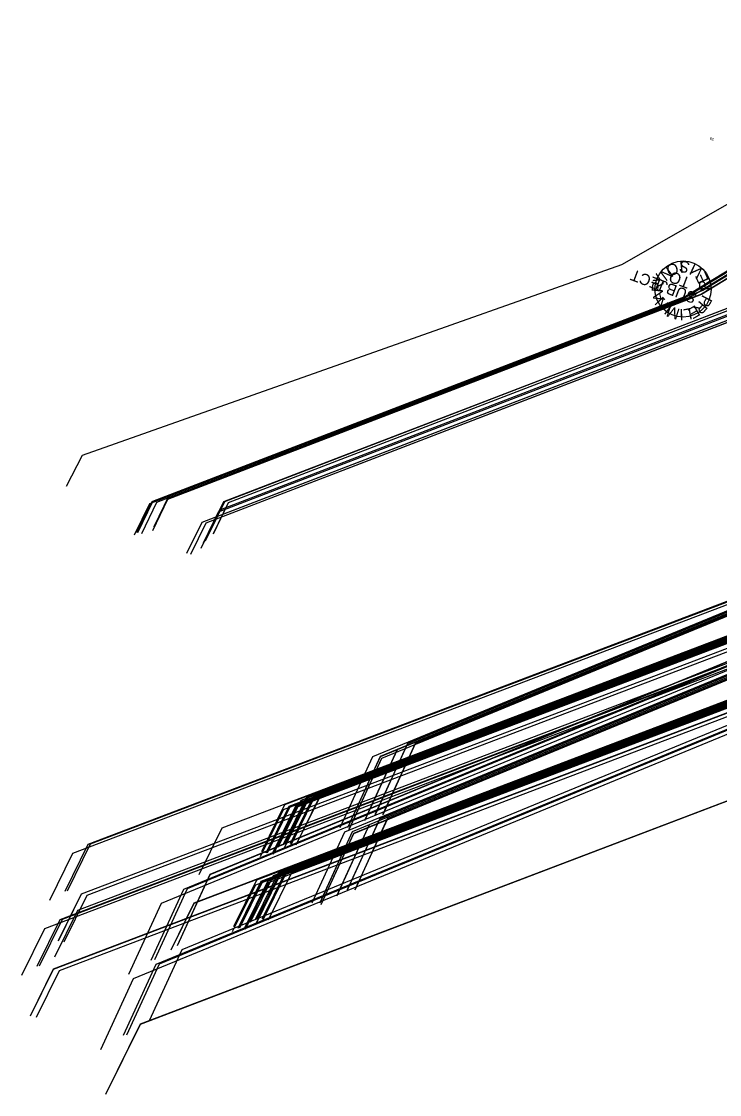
# Model space of a CAD drawing. Extents: x 1383350 to 1389654, y 1969292 to 1976308.
# Drawn here: x 1383350 to 1384913, y 1972123 to 1974524 of the extents above; entities that cross this region are included whole.
import ezdxf

# ---------------------------------------------------------------- set-up
doc = ezdxf.new("R2010")
doc.units = 0
for name, color, linetype in [('1', 7, 'Continuous'), ('R_Draft', 7, 'Continuous'), ('STAMP', 7, 'Continuous')]:
    doc.layers.add(name, color=color, linetype=linetype)

msp = doc.modelspace()

# ---------------------------------------------------------------- linework, layer by layer
at = {"layer": 'R_Draft'}
for p, q in [((1383486.4, 1973552.5), (1383450.4, 1973483.5)), ((1383486.3, 1973552.3), (1383450.4, 1973483.3)), ((1383486.3, 1973552.3), (1383450.4, 1973483.3)), ((1383680.3, 1973462.5), (1383646.2, 1973392.6)), ((1383680.2, 1973462.3), (1383646.2, 1973392.4)), ((1383680.2, 1973462.3), (1383646.2, 1973392.4)), ((1383637, 1973444.2), (1383602.9, 1973374.3)), ((1383637, 1973444.2), (1383602.9, 1973374.3)), ((1383637, 1973444.1), (1383602.9, 1973374.1)), ((1383641.8, 1973449.2), (1383607.7, 1973379.3)), ((1383643.9, 1973449.4), (1383609.8, 1973379.5)), ((1383643.9, 1973449.4), (1383609.8, 1973379.5)), ((1383643.9, 1973449.2), (1383609.8, 1973379.3)), ((1383652.7, 1973447.5), (1383618.6, 1973377.6)), ((1383652.7, 1973447.4), (1383618.6, 1973377.4)), ((1383652.7, 1973447.3), (1383618.6, 1973377.4)), ((1383677.4, 1973453.8), (1383643.3, 1973383.8)), ((1383677.4, 1973453.7), (1383643.3, 1973383.8)), ((1383677.4, 1973453.9), (1383643.4, 1973384)), ((1383802.3, 1973448.6), (1383768.3, 1973378.7)), ((1383804.4, 1973448.8), (1383770.3, 1973378.9)), ((1383804.4, 1973448.7), (1383770.3, 1973378.8)), ((1383804.4, 1973448.9), (1383770.4, 1973378.9)), ((1383813.2, 1973446.9), (1383779.1, 1973377)), ((1383813.2, 1973446.8), (1383779.1, 1973376.8)), ((1383813.2, 1973446.8), (1383779.1, 1973376.9)), ((1383785.5, 1973414.3), (1383751.4, 1973344.4)), ((1383785.5, 1973414.5), (1383751.5, 1973344.6)), ((1383785.6, 1973414.5), (1383751.5, 1973344.6)), ((1383790.7, 1973425.8), (1383756.6, 1973355.9)), ((1383790.8, 1973426), (1383756.7, 1973356)), ((1383790.8, 1973426), (1383756.7, 1973356.1)), ((1383795.6, 1973430.9), (1383761.5, 1973361)), ((1383753.9, 1973402.9), (1383719.8, 1973333)), ((1383753.9, 1973402.9), (1383719.8, 1973333)), ((1383753.9, 1973402.8), (1383719.8, 1973332.9)), ((1383762.7, 1973401), (1383728.6, 1973331.1)), ((1383762.7, 1973400.9), (1383728.6, 1973331)), ((1383762.7, 1973400.8), (1383728.6, 1973330.9)), ((1384214.4, 1972907.3), (1384141.4, 1972748.3)), ((1384214.4, 1972907.2), (1384141.4, 1972748.2)), ((1384214.5, 1972907.7), (1384141.5, 1972748.6)), ((1384231.6, 1972907.5), (1384158.6, 1972748.4)), ((1384231.7, 1972907.9), (1384158.7, 1972748.8)), ((1384231.6, 1972907.5), (1384158.7, 1972748.5)), ((1384191.2, 1972894), (1384118.2, 1972735)), ((1384191.3, 1972894.4), (1384118.3, 1972735.3)), ((1384191.3, 1972894.4), (1384118.3, 1972735.4)), ((1384136, 1972878.1), (1384063, 1972719.1)), ((1384153.2, 1972878.3), (1384080.2, 1972719.3)), ((1384153.3, 1972878.8), (1384080.3, 1972719.7)), ((1384153.3, 1972878.7), (1384080.3, 1972719.7)), ((1384155.9, 1972874.7), (1384082.9, 1972715.6)), ((1384155.8, 1972874.3), (1384082.9, 1972715.2)), ((1384155.9, 1972874.3), (1384082.9, 1972715.3)), ((1383988.4, 1972788.2), (1383936.9, 1972683.5)), ((1383991.5, 1972788.7), (1383940, 1972684)), ((1383991.5, 1972788.6), (1383940, 1972684)), ((1383991.5, 1972788.4), (1383940, 1972683.7)), ((1384003, 1972788.5), (1383951.5, 1972683.8)), ((1384003, 1972788.5), (1383951.5, 1972683.8)), ((1384002.9, 1972788.2), (1383951.5, 1972683.6)), ((1383938.7, 1972770.6), (1383887.2, 1972666)), ((1383948.7, 1972767.3), (1383897.3, 1972662.6)), ((1383951.9, 1972767.8), (1383900.4, 1972663.1)), ((1383951.9, 1972767.7), (1383900.4, 1972663)), ((1383951.8, 1972767.5), (1383900.4, 1972662.8)), ((1383963.3, 1972767.3), (1383911.8, 1972662.6)), ((1383963.4, 1972767.6), (1383911.9, 1972662.9)), ((1383963.4, 1972767.6), (1383911.9, 1972662.9)), ((1383965, 1972764.6), (1383913.5, 1972659.9)), ((1383965, 1972764.6), (1383913.5, 1972659.9)), ((1383965.1, 1972764.8), (1383913.6, 1972660.2)), ((1383975.8, 1972780.2), (1383924.3, 1972675.6)), ((1383989, 1972777.4), (1383937.5, 1972672.7)), ((1383989, 1972777.3), (1383937.5, 1972672.6)), ((1383989, 1972777.1), (1383937.5, 1972672.4)), ((1384004.7, 1972785.8), (1383953.2, 1972681.1)), ((1384004.6, 1972785.5), (1383953.2, 1972680.8)), ((1384004.7, 1972785.5), (1383953.2, 1972680.8)), ((1384016.1, 1972785.4), (1383964.6, 1972680.7)), ((1384016.1, 1972785.3), (1383964.6, 1972680.6)), ((1384016.2, 1972785.6), (1383964.7, 1972680.9)), ((1383936.2, 1972759.3), (1383884.7, 1972654.6)), ((1384151.9, 1972739), (1384078.9, 1972579.9)), ((1384151.9, 1972739), (1384078.9, 1972580)), ((1384152, 1972739.4), (1384079, 1972580.3)), ((1384169.1, 1972739.2), (1384096.1, 1972580.2)), ((1384169.1, 1972739.2), (1384096.1, 1972580.2)), ((1384169.2, 1972739.6), (1384096.2, 1972580.6)), ((1383798.9, 1972718.8), (1383747.4, 1972614.2)), ((1383798.9, 1972718.6), (1383747.4, 1972613.9)), ((1383798.9, 1972718.6), (1383747.4, 1972613.9)), ((1384128.7, 1972725.7), (1384055.7, 1972566.7)), ((1384128.8, 1972726.2), (1384055.8, 1972567.1)), ((1384128.8, 1972726.1), (1384055.8, 1972567.1)), ((1384073.4, 1972709.9), (1384000.5, 1972550.8)), ((1384090.7, 1972710.1), (1384017.7, 1972551)), ((1384090.7, 1972710.5), (1384017.8, 1972551.4)), ((1384090.7, 1972710.4), (1384017.8, 1972551.4)), ((1384093.3, 1972706), (1384020.3, 1972547)), ((1384093.4, 1972706.4), (1384020.4, 1972547.4)), ((1384093.3, 1972706.1), (1384020.4, 1972547)), ((1383498.6, 1972681.9), (1383447.1, 1972577.2)), ((1383498.6, 1972681.8), (1383447.1, 1972577.2)), ((1383503.9, 1972682.5), (1383452.4, 1972577.8)), ((1383464.3, 1972661.6), (1383412.8, 1972556.9)), ((1383925.8, 1972619.9), (1383874.4, 1972515.3)), ((1383929, 1972620.4), (1383877.5, 1972515.7)), ((1383929, 1972620.4), (1383877.5, 1972515.7)), ((1383928.9, 1972620.1), (1383877.5, 1972515.4)), ((1383940.4, 1972620), (1383888.9, 1972515.3)), ((1383940.5, 1972620.2), (1383889, 1972515.5)), ((1383940.5, 1972620.2), (1383889, 1972515.6)), ((1383771.8, 1972614.6), (1383698.8, 1972455.6)), ((1383771.8, 1972614.5), (1383698.8, 1972455.5)), ((1383876.2, 1972602.4), (1383824.7, 1972497.7)), ((1383886.2, 1972599), (1383834.7, 1972494.3)), ((1383889.3, 1972599.2), (1383837.8, 1972494.5)), ((1383889.4, 1972599.5), (1383837.9, 1972494.8)), ((1383889.4, 1972599.4), (1383837.9, 1972494.8)), ((1383900.8, 1972599), (1383849.3, 1972494.4)), ((1383900.9, 1972599.3), (1383849.4, 1972494.6)), ((1383900.9, 1972599.3), (1383849.4, 1972494.6)), ((1383902.5, 1972596.3), (1383851, 1972491.6)), ((1383902.5, 1972596.3), (1383851, 1972491.6)), ((1383902.6, 1972596.6), (1383851.1, 1972491.9)), ((1383913.3, 1972612), (1383861.8, 1972507.3)), ((1383926.5, 1972609.1), (1383875, 1972504.4)), ((1383926.5, 1972609), (1383875, 1972504.4)), ((1383926.4, 1972608.8), (1383875, 1972504.1)), ((1383942.1, 1972617.2), (1383890.6, 1972512.5)), ((1383942.1, 1972617.2), (1383890.6, 1972512.6)), ((1383942.2, 1972617.5), (1383890.7, 1972512.8)), ((1383953.6, 1972617.1), (1383902.1, 1972512.4)), ((1383953.6, 1972617), (1383902.1, 1972512.4)), ((1383953.7, 1972617.3), (1383902.2, 1972512.6)), ((1383483.7, 1972570.8), (1383432.2, 1972466.1)), ((1383483.7, 1972570.8), (1383432.2, 1972466.2)), ((1383483.8, 1972571.1), (1383432.3, 1972466.4)), ((1383713.2, 1972581.6), (1383640.2, 1972422.5)), ((1383713.2, 1972581.6), (1383640.2, 1972422.6)), ((1383721.2, 1972582.8), (1383648.2, 1972423.7)), ((1383873.7, 1972591.1), (1383822.2, 1972486.4)), ((1383496.9, 1972567.9), (1383445.4, 1972463.2)), ((1383662.6, 1972549.8), (1383589.7, 1972390.8)), ((1383736.4, 1972550.6), (1383684.9, 1972445.9)), ((1383736.4, 1972550.3), (1383684.9, 1972445.6)), ((1383736.4, 1972550.3), (1383684.9, 1972445.6)), ((1383475.7, 1972534.5), (1383424.2, 1972429.8)), ((1383475.7, 1972534.5), (1383424.2, 1972429.8)), ((1383436.1, 1972513.6), (1383384.6, 1972408.9)), ((1383436.1, 1972513.6), (1383384.6, 1972408.9)), ((1383441.4, 1972514.2), (1383389.9, 1972409.5)), ((1383401.8, 1972493.3), (1383350.3, 1972388.6)), ((1383709.3, 1972446.3), (1383636.3, 1972287.2)), ((1383709.3, 1972446.3), (1383636.3, 1972287.3)), ((1383421.2, 1972402.8), (1383369.7, 1972298.1)), ((1383421.2, 1972402.6), (1383369.7, 1972297.9)), ((1383421.2, 1972402.5), (1383369.7, 1972297.9)), ((1383650.7, 1972413.4), (1383577.7, 1972254.3)), ((1383650.7, 1972413.3), (1383577.7, 1972254.3)), ((1383658.7, 1972414.5), (1383585.7, 1972255.4)), ((1383434.4, 1972399.6), (1383382.9, 1972295)), ((1383600.1, 1972381.5), (1383527.1, 1972222.5)), ((1383615.9, 1972279.6), (1383538.6, 1972122.5)), ((1383615.9, 1972279.6), (1383538.6, 1972122.6)), ((1383616, 1972280), (1383538.7, 1972123))]:
    msp.add_line(p, q, dxfattribs=at)
for points in [[(1387690, 1974523.2), (1386878, 1974003.2), (1384214.4, 1972907.3)], [(1387690, 1974523.1), (1386878, 1974003.2), (1384214.4, 1972907.2)], [(1387690.1, 1974523.5), (1386878.1, 1974003.6), (1384214.5, 1972907.7)], [(1387707.2, 1974523.4), (1386895.2, 1974003.4), (1384231.6, 1972907.5)], [(1387707.2, 1974523.3), (1386895.2, 1974003.4), (1384231.6, 1972907.5)], [(1387707.3, 1974523.8), (1386895.3, 1974003.8), (1384231.7, 1972907.9)], [(1387611.6, 1974494), (1386799.6, 1973974), (1384136, 1972878.1)], [(1387628.8, 1974494.2), (1386816.8, 1973974.3), (1384153.2, 1972878.3)], [(1387628.8, 1974494.6), (1386816.9, 1973974.6), (1384153.3, 1972878.7)], [(1387628.9, 1974494.6), (1386816.9, 1973974.7), (1384153.3, 1972878.8)], [(1387666.8, 1974509.9), (1386854.8, 1973989.9), (1384191.2, 1972894)], [(1387666.9, 1974510.3), (1386854.9, 1973990.3), (1384191.3, 1972894.4)], [(1387666.9, 1974510.3), (1386854.9, 1973990.4), (1384191.3, 1972894.4)], [(1387631.4, 1974490.1), (1386819.4, 1973970.2), (1384155.8, 1972874.3)], [(1387631.5, 1974490.6), (1386819.5, 1973970.6), (1384155.9, 1972874.7)], [(1387631.4, 1974490.2), (1386819.5, 1973970.2), (1384155.9, 1972874.3)], [(1387627.5, 1974354.9), (1386815.5, 1973834.9), (1384151.9, 1972739)], [(1387627.5, 1974354.8), (1386815.5, 1973834.9), (1384151.9, 1972739)], [(1387627.6, 1974355.3), (1386815.6, 1973835.3), (1384152, 1972739.4)], [(1387644.7, 1974355.1), (1386832.7, 1973835.1), (1384169.1, 1972739.2)], [(1387644.7, 1974355.1), (1386832.7, 1973835.2), (1384169.1, 1972739.2)], [(1387644.8, 1974355.5), (1386832.8, 1973835.5), (1384169.2, 1972739.6)], [(1387549, 1974325.7), (1386737, 1973805.8), (1384073.4, 1972709.9)], [(1387566.3, 1974326.4), (1386754.4, 1973806.4), (1384090.7, 1972710.5)], [(1387566.3, 1974326.3), (1386754.3, 1973806.4), (1384090.7, 1972710.4)], [(1387566.3, 1974325.9), (1386754.3, 1973806), (1384090.7, 1972710.1)], [(1387604.3, 1974341.6), (1386792.3, 1973821.7), (1384128.7, 1972725.7)], [(1387604.4, 1974342), (1386792.4, 1973822), (1384128.8, 1972726.1)], [(1387604.4, 1974342), (1386792.4, 1973822.1), (1384128.8, 1972726.2)], [(1387568.9, 1974321.9), (1386756.9, 1973801.9), (1384093.3, 1972706)], [(1387568.9, 1974321.9), (1386756.9, 1973802), (1384093.3, 1972706.1)], [(1387569, 1974322.3), (1386757, 1973802.3), (1384093.4, 1972706.4)], [(1387247.4, 1974230.5), (1386435.4, 1973710.5), (1383771.8, 1972614.6)], [(1387247.4, 1974230.4), (1386435.4, 1973710.5), (1383771.8, 1972614.5)], [(1385065.2, 1974191.9), (1384693.1, 1973979.2), (1383486.3, 1973552.3)], [(1385065.2, 1974191.9), (1384693.1, 1973979.2), (1383486.3, 1973552.3)], [(1385065.2, 1974192.1), (1384693.2, 1973979.4), (1383486.4, 1973552.5)], [(1387188.8, 1974197.5), (1386376.8, 1973677.5), (1383713.2, 1972581.6)], [(1387188.8, 1974197.4), (1386376.8, 1973677.5), (1383713.2, 1972581.6)], [(1387196.8, 1974198.6), (1386384.8, 1973678.7), (1383721.2, 1972582.8)], [(1387138.2, 1974165.7), (1386326.3, 1973645.7), (1383662.6, 1972549.8)], [(1385202.8, 1974131.1), (1384836.7, 1973908.5), (1383641.8, 1973449.2)], [(1385204.9, 1974131.4), (1384838.8, 1973908.8), (1383643.9, 1973449.4)], [(1385204.9, 1974131.3), (1384838.8, 1973908.7), (1383643.9, 1973449.4)], [(1385204.9, 1974131.2), (1384838.7, 1973908.6), (1383643.9, 1973449.2)], [(1385238.5, 1974135.9), (1384872.3, 1973913.2), (1383677.4, 1973453.9)], [(1385238.4, 1974135.7), (1384872.3, 1973913.1), (1383677.4, 1973453.7)], [(1385238.4, 1974135.7), (1384872.3, 1973913.1), (1383677.4, 1973453.8)], [(1385241.3, 1974144.3), (1384875.1, 1973921.6), (1383680.2, 1973462.3)], [(1385241.3, 1974144.2), (1384875.1, 1973921.6), (1383680.2, 1973462.3)], [(1385241.3, 1974144.4), (1384875.1, 1973921.8), (1383680.3, 1973462.5)], [(1385363.4, 1974130.6), (1384997.2, 1973907.9), (1383802.3, 1973448.6)], [(1385365.5, 1974130.8), (1384999.3, 1973908.2), (1383804.4, 1973448.8)], [(1385365.5, 1974130.8), (1384999.3, 1973908.2), (1383804.4, 1973448.9)], [(1385365.4, 1974130.6), (1384999.3, 1973908), (1383804.4, 1973448.7)], [(1385198, 1974126.2), (1384831.9, 1973903.5), (1383637, 1973444.2)], [(1385198, 1974126.2), (1384831.9, 1973903.6), (1383637, 1973444.2)], [(1385198, 1974126), (1384831.8, 1973903.4), (1383637, 1973444.1)], [(1385213.7, 1974129.5), (1384847.6, 1973906.8), (1383652.7, 1973447.5)], [(1385213.7, 1974129.3), (1384847.5, 1973906.7), (1383652.7, 1973447.3)], [(1385213.7, 1974129.3), (1384847.5, 1973906.7), (1383652.7, 1973447.4)], [(1385351.8, 1974107.7), (1384985.6, 1973885.1), (1383790.7, 1973425.8)], [(1385351.8, 1974107.9), (1384985.6, 1973885.3), (1383790.8, 1973426)], [(1385351.8, 1974107.9), (1384985.6, 1973885.3), (1383790.8, 1973426)], [(1385356.6, 1974112.9), (1384990.4, 1973890.2), (1383795.6, 1973430.9)], [(1385374.3, 1974128.9), (1385008.1, 1973906.3), (1383813.2, 1973446.9)], [(1385374.2, 1974128.7), (1385008, 1973906.1), (1383813.2, 1973446.8)], [(1385374.2, 1974128.7), (1385008.1, 1973906.1), (1383813.2, 1973446.8)], [(1385314.9, 1974084.9), (1384948.8, 1973862.2), (1383753.9, 1973402.9)], [(1385315, 1974084.9), (1384948.8, 1973862.3), (1383753.9, 1973402.9)], [(1385314.9, 1974084.7), (1384948.7, 1973862.1), (1383753.9, 1973402.8)], [(1385323.7, 1974083), (1384957.6, 1973860.4), (1383762.7, 1973401)], [(1385323.7, 1974082.8), (1384957.5, 1973860.2), (1383762.7, 1973400.8)], [(1385323.7, 1974082.8), (1384957.5, 1973860.2), (1383762.7, 1973400.9)], [(1385346.6, 1974096.4), (1384980.4, 1973873.8), (1383785.5, 1973414.5)], [(1385346.6, 1974096.3), (1384980.4, 1973873.7), (1383785.5, 1973414.3)], [(1385346.6, 1974096.5), (1384980.4, 1973873.9), (1383785.6, 1973414.5)], [(1387184.9, 1974062.2), (1386372.9, 1973542.2), (1383709.3, 1972446.3)], [(1387184.9, 1974062.1), (1386372.9, 1973542.2), (1383709.3, 1972446.3)], [(1387126.3, 1974029.2), (1386314.3, 1973509.2), (1383650.7, 1972413.3)], [(1387126.3, 1974029.2), (1386314.3, 1973509.3), (1383650.7, 1972413.4)], [(1387134.3, 1974030.4), (1386322.3, 1973510.4), (1383658.7, 1972414.5)], [(1387075.7, 1973997.4), (1386263.7, 1973477.4), (1383600.1, 1972381.5)], [(1387133.8, 1973801.2), (1386308.1, 1973303.3), (1383615.9, 1972279.6)], [(1387133.8, 1973801.1), (1386308.1, 1973303.3), (1383615.9, 1972279.6)], [(1387133.9, 1973801.5), (1386308.1, 1973303.7), (1383616, 1972280)], [(1386321.1, 1973794.6), (1385770.6, 1973462.7), (1383975.8, 1972780.2)], [(1386333.6, 1973802.6), (1385783.2, 1973470.7), (1383988.4, 1972788.2)], [(1386336.8, 1973803.1), (1385786.3, 1973471.1), (1383991.5, 1972788.7)], [(1386336.8, 1973803), (1385786.3, 1973471.1), (1383991.5, 1972788.6)], [(1386336.7, 1973802.8), (1385786.3, 1973470.9), (1383991.5, 1972788.4)], [(1386348.2, 1973802.6), (1385797.7, 1973470.7), (1384002.9, 1972788.2)], [(1386348.3, 1973802.9), (1385797.8, 1973470.9), (1384003, 1972788.5)], [(1386348.3, 1973802.9), (1385797.8, 1973471), (1384003, 1972788.5)], [(1386349.9, 1973799.9), (1385799.4, 1973467.9), (1384004.6, 1972785.5)], [(1386350, 1973800.1), (1385799.5, 1973468.2), (1384004.7, 1972785.8)], [(1386349.9, 1973799.9), (1385799.4, 1973468), (1384004.7, 1972785.5)], [(1386361.4, 1973799.7), (1385810.9, 1973467.8), (1384016.1, 1972785.3)], [(1386361.4, 1973799.7), (1385810.9, 1973467.8), (1384016.1, 1972785.4)], [(1386361.5, 1973800), (1385811, 1973468.1), (1384016.2, 1972785.6)], [(1386281.5, 1973773.7), (1385731, 1973441.8), (1383936.2, 1972759.3)], [(1386284, 1973785), (1385733.5, 1973453.1), (1383938.7, 1972770.6)], [(1386294, 1973781.7), (1385743.5, 1973449.8), (1383948.7, 1972767.3)], [(1386297.1, 1973781.9), (1385746.6, 1973449.9), (1383951.8, 1972767.5)], [(1386297.2, 1973782.1), (1385746.7, 1973450.2), (1383951.9, 1972767.7)], [(1386297.2, 1973782.1), (1385746.7, 1973450.2), (1383951.9, 1972767.8)], [(1386308.6, 1973781.7), (1385758.1, 1973449.8), (1383963.3, 1972767.3)], [(1386308.7, 1973782), (1385758.2, 1973450.1), (1383963.4, 1972767.6)], [(1386308.6, 1973781.9), (1385758.2, 1973450), (1383963.4, 1972767.6)], [(1386310.3, 1973779), (1385759.8, 1973447.1), (1383965, 1972764.6)], [(1386310.3, 1973778.9), (1385759.8, 1973447), (1383965, 1972764.6)], [(1386310.4, 1973779.2), (1385759.9, 1973447.3), (1383965.1, 1972764.8)], [(1386334.3, 1973791.7), (1385783.8, 1973459.8), (1383989, 1972777.3)], [(1386334.3, 1973791.7), (1385783.8, 1973459.8), (1383989, 1972777.4)], [(1386334.2, 1973791.5), (1385783.8, 1973459.5), (1383989, 1972777.1)], [(1386144.2, 1973733.2), (1385593.7, 1973401.3), (1383798.9, 1972718.8)], [(1386144.2, 1973733), (1385593.7, 1973401.1), (1383798.9, 1972718.6)], [(1386144.1, 1973732.9), (1385593.7, 1973401), (1383798.9, 1972718.6)], [(1385809.6, 1973675.9), (1385259.1, 1973344), (1383464.3, 1972661.6)], [(1385843.9, 1973696.2), (1385293.4, 1973364.3), (1383498.6, 1972681.8)], [(1385843.9, 1973696.2), (1385293.4, 1973364.3), (1383498.6, 1972681.9)], [(1385849.2, 1973696.9), (1385298.7, 1973364.9), (1383503.9, 1972682.5)], [(1386258.6, 1973626.4), (1385708.1, 1973294.4), (1383913.3, 1972612)], [(1386271.1, 1973634.3), (1385720.6, 1973302.4), (1383925.8, 1972619.9)], [(1386274.2, 1973634.5), (1385723.7, 1973302.6), (1383928.9, 1972620.1)], [(1386274.3, 1973634.8), (1385723.8, 1973302.9), (1383929, 1972620.4)], [(1386274.3, 1973634.7), (1385723.8, 1973302.8), (1383929, 1972620.4)], [(1386285.7, 1973634.3), (1385735.2, 1973302.4), (1383940.4, 1972620)], [(1386285.7, 1973634.6), (1385735.3, 1973302.7), (1383940.5, 1972620.2)], [(1386285.8, 1973634.6), (1385735.3, 1973302.7), (1383940.5, 1972620.2)], [(1386287.4, 1973631.6), (1385736.9, 1973299.7), (1383942.1, 1972617.2)], [(1386287.4, 1973631.6), (1385736.9, 1973299.7), (1383942.1, 1972617.2)], [(1386287.5, 1973631.9), (1385737, 1973299.9), (1383942.2, 1972617.5)], [(1386298.9, 1973631.5), (1385748.4, 1973299.5), (1383953.6, 1972617.1)], [(1386298.9, 1973631.4), (1385748.4, 1973299.5), (1383953.6, 1972617)], [(1386298.9, 1973631.7), (1385748.5, 1973299.8), (1383953.7, 1972617.3)], [(1386219, 1973605.4), (1385668.5, 1973273.5), (1383873.7, 1972591.1)], [(1386221.5, 1973616.8), (1385671, 1973284.8), (1383876.2, 1972602.4)], [(1386231.5, 1973613.4), (1385681, 1973281.5), (1383886.2, 1972599)], [(1386234.6, 1973613.6), (1385684.1, 1973281.7), (1383889.3, 1972599.2)], [(1386234.7, 1973613.9), (1385684.2, 1973281.9), (1383889.4, 1972599.5)], [(1386234.6, 1973613.8), (1385684.2, 1973281.9), (1383889.4, 1972599.4)], [(1386246.1, 1973613.4), (1385695.6, 1973281.5), (1383900.8, 1972599)], [(1386246.1, 1973613.7), (1385695.7, 1973281.8), (1383900.9, 1972599.3)], [(1386246.1, 1973613.7), (1385695.7, 1973281.8), (1383900.9, 1972599.3)], [(1386247.8, 1973610.7), (1385697.3, 1973278.7), (1383902.5, 1972596.3)], [(1386247.8, 1973610.7), (1385697.3, 1973278.8), (1383902.5, 1972596.3)], [(1386247.8, 1973610.9), (1385697.4, 1973279), (1383902.6, 1972596.6)], [(1386271.7, 1973623.2), (1385721.2, 1973291.3), (1383926.4, 1972608.8)], [(1386271.8, 1973623.5), (1385721.3, 1973291.5), (1383926.5, 1972609.1)], [(1386271.8, 1973623.4), (1385721.3, 1973291.5), (1383926.5, 1972609)], [(1385829, 1973585.2), (1385278.5, 1973253.3), (1383483.7, 1972570.8)], [(1385829, 1973585.2), (1385278.5, 1973253.3), (1383483.7, 1972570.8)], [(1385829, 1973585.5), (1385278.5, 1973253.5), (1383483.8, 1972571.1)], [(1385842.1, 1973582.3), (1385291.7, 1973250.4), (1383496.9, 1972567.9)], [(1386081.7, 1973564.9), (1385531.2, 1973233), (1383736.4, 1972550.6)], [(1386081.6, 1973564.7), (1385531.2, 1973232.7), (1383736.4, 1972550.3)], [(1386081.6, 1973564.7), (1385531.2, 1973232.8), (1383736.4, 1972550.3)], [(1385821, 1973548.9), (1385270.5, 1973216.9), (1383475.7, 1972534.5)], [(1385821, 1973548.9), (1385270.5, 1973217), (1383475.7, 1972534.5)], [(1385747.1, 1973507.7), (1385196.6, 1973175.8), (1383401.8, 1972493.3)], [(1385781.3, 1973528), (1385230.9, 1973196.1), (1383436.1, 1972513.6)], [(1385781.3, 1973527.9), (1385230.9, 1973196), (1383436.1, 1972513.6)], [(1385786.7, 1973528.6), (1385236.2, 1973196.7), (1383441.4, 1972514.2)], [(1385766.5, 1973417.2), (1385216, 1973085.3), (1383421.2, 1972402.8)], [(1385766.4, 1973416.9), (1385216, 1973085), (1383421.2, 1972402.5)], [(1385766.4, 1973416.9), (1385216, 1973085), (1383421.2, 1972402.6)], [(1385779.6, 1973414), (1385229.2, 1973082.1), (1383434.4, 1972399.6)]]:
    msp.add_lwpolyline(points, dxfattribs=at)
at = {"layer": 'STAMP'}
msp.add_circle((1384830.9, 1973924.9), 62.9, dxfattribs=at)

# ---------------------------------------------------------------- texts
at = {"layer": '1'}
msp.add_text('59', height=6, rotation=159.6183, dxfattribs=at).set_placement((1384900.8, 1974261.8))
at = {"layer": 'STAMP'}
for s, height, rotation, p in [('S', 25.3, 164.973, (1384848, 1973983.9)), ('SUBJECT', 25.31, 159.2411, (1384863.9, 1973915.1)), ('N', 25.3, 216.3788, (1384796.7, 1973976)), ('O', 25.3, 195.8165, (1384816.4, 1973984.6)), ('TO', 25.31, 159.2411, (1384849.4, 1973949)), ('I', 25.3, 185.5354, (1384830.9, 1973986.6)), ('I', 25.3, 154.6919, (1384861.6, 1973978.3)), ('V', 25.3, 134.1296, (1384879.6, 1973962.9)), ('E', 25.3, 113.5673, (1384889.3, 1973944.4)), ('R', 25.3, 84.6704, (1384785.4, 1973916.4)), ('Y', 25.3, 65.3542, (1384784.8, 1973931.1)), ('R', 25.3, 93.0049, (1384892.5, 1973922)), ('A', 25.3, 103.9867, (1384791.1, 1973900.5)), ('N', 25.3, 132.961, (1384800.6, 1973892.1)), ('R', 25.3, 229.5422, (1384868.6, 1973900.6)), ('P', 25.3, 241.85, (1384875.3, 1973913.7)), ('I', 25.3, 142.6191, (1384808.9, 1973885.7)), ('M', 25.3, 161.9354, (1384825.7, 1973879.8)), ('I', 25.3, 181.2516, (1384831.8, 1973880.4)), ('L', 25.3, 190.9097, (1384848.5, 1973883)), ('E', 25.3, 210.226, (1384859.1, 1973889.9))]:
    msp.add_text(s, height=height, rotation=rotation, dxfattribs=at).set_placement(p)

doc.saveas('drawing.dxf')
